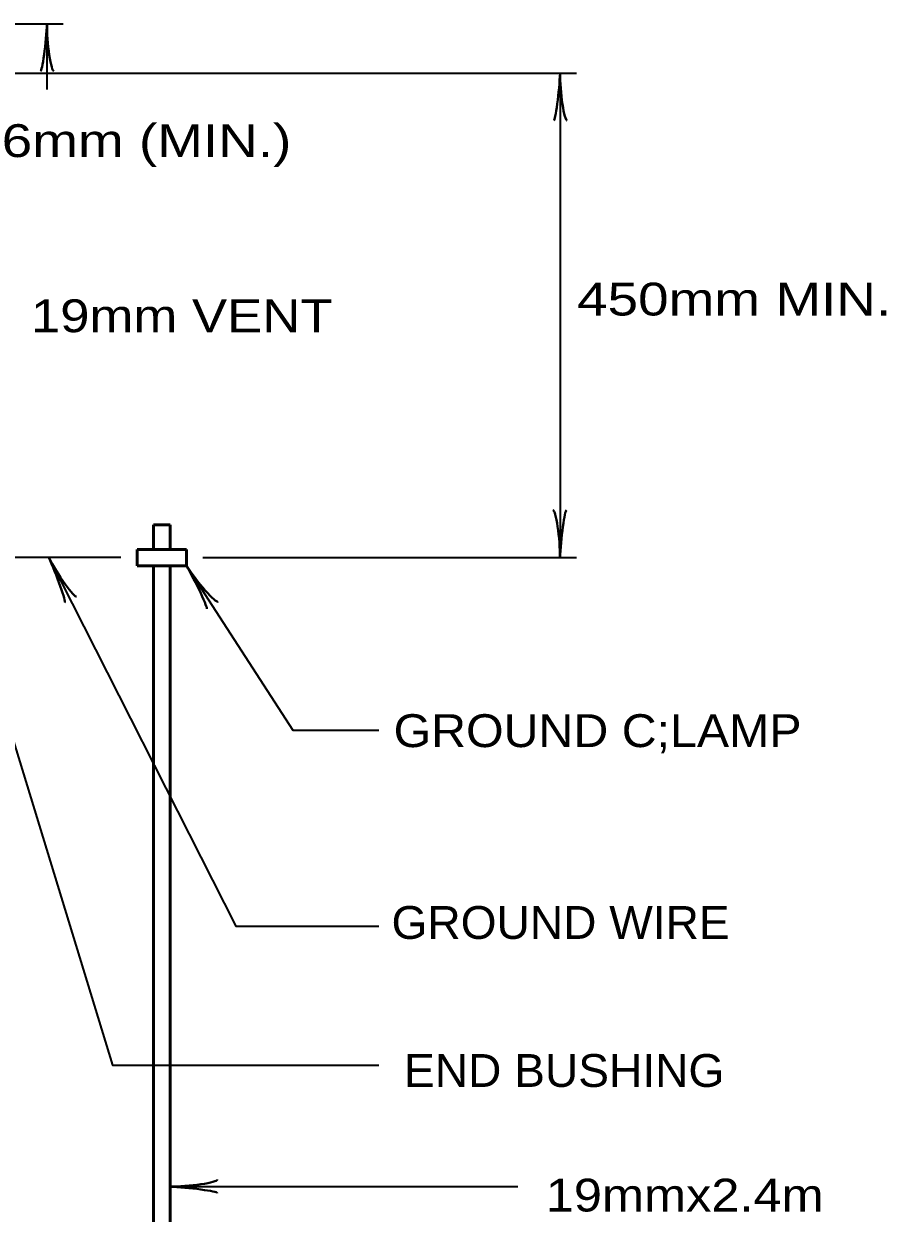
# Model space of a CAD drawing. Extents: x -31 to 824, y -13 to 531.
# Drawn here: x 556.7 to 619.7, y 166.1 to 253.1 of the extents above; entities that cross this region are included whole.
import ezdxf

# ---------------------------------------------------------------- set-up
doc = ezdxf.new("R2010")
doc.units = 0
doc.header["$LTSCALE"] = 1.2
doc.layers.add('1', color=7, linetype='Continuous', lineweight=35)

msp = doc.modelspace()

# ---------------------------------------------------------------- linework, layer by layer
at = {"layer": '1'}
for p, q in [((542.758, 253.04), (559.558, 253.04)), ((558.358, 253.04), (558.358, 248.24)), ((551.457, 249.44), (597.058, 249.44)), ((595.858, 249.44), (595.858, 214.04)), ((563.758, 214.04), (553.258, 214.04)), ((569.758, 214.04), (597.058, 214.04)), ((567.358, 168.063), (592.776, 168.063))]:
    msp.add_line(p, q, dxfattribs=at)
at = {"layer": '1', "lineweight": 53}
for p, q in [((566.158, 216.44), (567.358, 216.44)), ((566.158, 216.44), (566.158, 214.64)), ((567.358, 216.44), (567.358, 214.64)), ((564.957, 213.44), (564.957, 214.64)), ((564.957, 214.64), (568.558, 214.64)), ((568.558, 213.44), (568.558, 214.64)), ((564.957, 213.44), (568.558, 213.44)), ((566.158, 213.44), (566.158, 163.64)), ((567.358, 213.44), (567.358, 163.04))]:
    msp.add_line(p, q, dxfattribs=at)
at = {"layer": '1'}
for points in [[(558.508, 214.04), (572.17, 187.1), (582.616, 187.1)], [(552.058, 213.14), (563.156, 176.937), (582.616, 176.937)], [(568.558, 213.44), (576.32, 201.414), (582.616, 201.414)]]:
    msp.add_lwpolyline(points, dxfattribs=at)
at = {"layer": '1', "lineweight": 40}
for centre, major_axis, ratio, start_param, end_param in [((558.104, 251.696), (0.211, 2.108), 0.07063, 3.140715, 5.41811), ((558.689, 251.731), (-0.187, 2.143), 0.122415, 0.896353, 3.141593), ((595.604, 248.096), (0.211, 2.108), 0.07063, 3.140715, 5.41811), ((595.604, 248.096), (0.211, 2.108), 0.07063, 3.140715, 5.41811), ((596.189, 248.131), (-0.187, 2.143), 0.122415, 0.896353, 3.141593), ((596.189, 248.131), (-0.187, 2.143), 0.122415, 0.896353, 3.141593), ((595.526, 215.35), (0.187, -2.143), 0.122415, 0.896353, 3.141593), ((596.111, 215.385), (-0.211, -2.108), 0.07063, 3.140715, 5.41811), ((558.889, 212.726), (0.765, -1.975), 0.07063, 6.282307, 8.559703), ((558.889, 212.726), (0.765, -1.975), 0.07063, 6.282307, 8.559703), ((559.395, 213.022), (-1.136, 1.826), 0.122415, 0.896353, 3.141593), ((559.395, 213.022), (-1.136, 1.826), 0.122415, 0.896353, 3.141593), ((569.073, 212.173), (0.966, -1.885), 0.07063, 6.282307, 8.559703), ((569.546, 212.52), (-1.32, 1.699), 0.122415, 0.896353, 3.141593), ((568.702, 167.809), (-2.108, 0.211), 0.07063, 3.140715, 5.41811), ((568.667, 168.394), (-2.143, -0.187), 0.122415, 0.896353, 3.141593)]:
    msp.add_ellipse(centre, major_axis=major_axis, ratio=ratio, start_param=start_param, end_param=end_param, dxfattribs=at)

# ---------------------------------------------------------------- texts
at = {"layer": '1'}
for s, width, p in [('6mm (MIN.)', 1.25, (555.055, 243.311)), ('450mm MIN.', 1.25, (597.097, 231.73)), ('19mm VENT', 1.2, (557.188, 230.511)), ('GROUND C;LAMP', 1.1, (583.692, 200.189)), ('GROUND WIRE', 1.05, (583.54, 186.17)), ('END BUSHING', 1.05, (584.454, 175.352)), ('19mmx2.4m', 1.15, (594.812, 166.247))]:
    msp.add_text(s, height=2.4, dxfattribs=dict(at, width=width)).set_placement(p)

doc.saveas('drawing.dxf')
